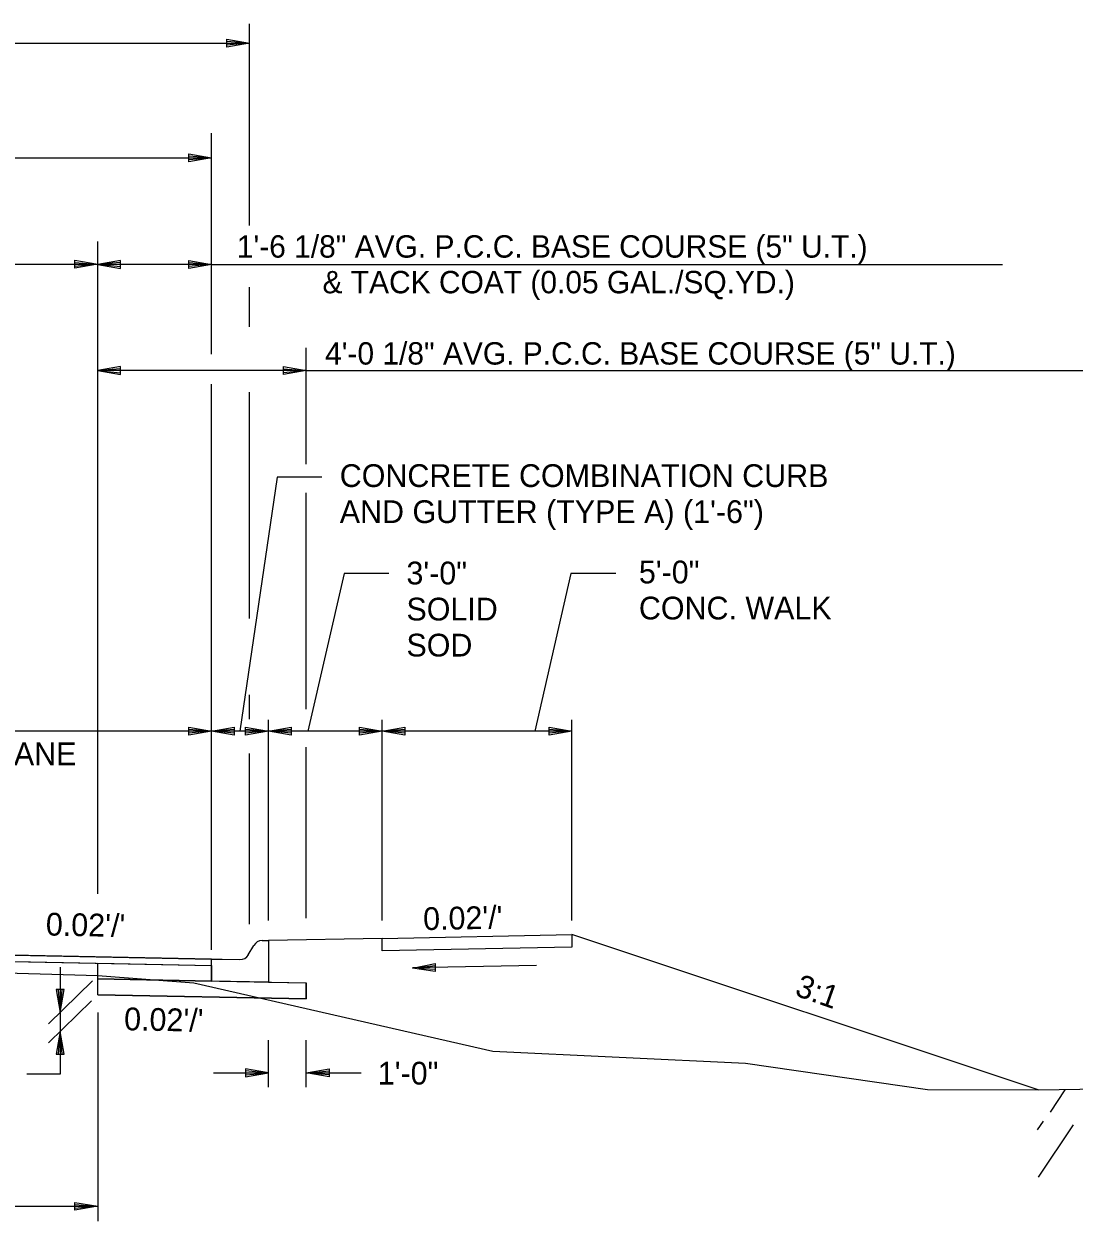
# Model space of a CAD drawing. Extents: x 1001270 to 1003428, y 1840152 to 1842912.
# Drawn here: x 1001348.15 to 1001375.83, y 1841972.67 to 1842004.22 of the extents above; entities that cross this region are included whole.
import ezdxf

# ---------------------------------------------------------------- set-up
doc = ezdxf.new("R2010")
doc.units = 0
for name, color, linetype in [('19', 7, 'Continuous'), ('20', 7, 'Continuous'), ('8', 7, 'Continuous')]:
    doc.layers.add(name, color=color, linetype=linetype)

# ---------------------------------------------------------------- blocks, each defined once
blk = doc.blocks.new('TM')
at = {"layer": '8'}
for p, q in [((-120.309, 21.181), (-119.787, -20.829)), ((0, 0), (-120.309, 21.181)), ((-31.382, 2.945), (-120.176, 10.512)), ((-119.787, -20.829), (0, 0)), ((-119.911, -10.826), (-31.307, -3.057))]:
    blk.add_line(p, q, dxfattribs=at)

msp = doc.modelspace()

# ---------------------------------------------------------------- linework, layer by layer
at = {"layer": '19'}
for p, q in [((1001354.093, 1841998.907), (1001354.093, 1842004.222)), ((1001353.493, 1842003.614), (1001353.493, 1842003.824)), ((1001353.493, 1842003.824), (1001354.093, 1842003.719)), ((1001353.493, 1842003.769), (1001353.933, 1842003.734)), ((1001316.093, 1842003.719), (1001354.093, 1842003.719)), ((1001354.093, 1842003.719), (1001353.493, 1842003.614)), ((1001353.933, 1842003.704), (1001353.493, 1842003.664)), ((1001353.092, 1841995.519), (1001353.092, 1842001.344)), ((1001317.092, 1842000.692), (1001353.092, 1842000.692)), ((1001352.493, 1842000.587), (1001352.493, 1842000.797)), ((1001352.493, 1842000.797), (1001353.093, 1842000.692)), ((1001352.493, 1842000.742), (1001352.933, 1842000.707)), ((1001353.093, 1842000.692), (1001352.493, 1842000.587)), ((1001352.933, 1842000.677), (1001352.493, 1842000.637)), ((1001350.092, 1841981.291), (1001350.092, 1841998.484)), ((1001320.092, 1841997.886), (1001350.092, 1841997.886)), ((1001349.492, 1841997.781), (1001349.492, 1841997.991)), ((1001349.492, 1841997.991), (1001350.092, 1841997.886)), ((1001349.492, 1841997.936), (1001349.932, 1841997.901)), ((1001350.092, 1841997.886), (1001349.492, 1841997.781)), ((1001349.932, 1841997.871), (1001349.492, 1841997.831)), ((1001350.692, 1841997.989), (1001350.092, 1841997.884)), ((1001353.092, 1841997.884), (1001350.092, 1841997.884)), ((1001350.092, 1841997.884), (1001350.692, 1841997.779)), ((1001350.692, 1841997.934), (1001350.252, 1841997.899)), ((1001350.252, 1841997.869), (1001350.692, 1841997.829)), ((1001350.692, 1841997.779), (1001350.692, 1841997.989)), ((1001352.492, 1841997.779), (1001352.492, 1841997.989)), ((1001352.492, 1841997.989), (1001353.092, 1841997.884)), ((1001352.492, 1841997.934), (1001352.932, 1841997.899)), ((1001353.092, 1841997.884), (1001352.492, 1841997.779)), ((1001352.932, 1841997.869), (1001352.492, 1841997.829)), ((1001353.092, 1841997.884), (1001373.944, 1841997.884)), ((1001354.092, 1841996.238), (1001354.092, 1841997.28)), ((1001355.592, 1841992.621), (1001355.592, 1841995.684)), ((1001350.692, 1841995.189), (1001350.092, 1841995.084)), ((1001355.592, 1841995.084), (1001350.092, 1841995.084)), ((1001350.092, 1841995.084), (1001350.692, 1841994.979)), ((1001350.692, 1841995.134), (1001350.252, 1841995.099)), ((1001350.252, 1841995.069), (1001350.692, 1841995.029)), ((1001350.692, 1841994.979), (1001350.692, 1841995.189)), ((1001354.992, 1841994.979), (1001354.992, 1841995.189)), ((1001354.992, 1841995.189), (1001355.592, 1841995.084)), ((1001354.992, 1841995.134), (1001355.432, 1841995.099)), ((1001355.592, 1841995.084), (1001354.992, 1841994.979)), ((1001355.432, 1841995.069), (1001354.992, 1841995.029)), ((1001355.592, 1841995.084), (1001376.275, 1841995.084)), ((1001353.092, 1841979.814), (1001353.092, 1841994.724)), ((1001354.092, 1841988.55), (1001354.092, 1841994.519)), ((1001354.823, 1841992.275), (1001353.835, 1841985.583)), ((1001356.002, 1841992.275), (1001354.823, 1841992.275)), ((1001355.592, 1841986.161), (1001355.592, 1841991.861)), ((1001356.587, 1841989.74), (1001355.63, 1841985.583)), ((1001357.766, 1841989.74), (1001356.587, 1841989.74)), ((1001362.569, 1841989.74), (1001361.613, 1841985.583)), ((1001363.748, 1841989.74), (1001362.569, 1841989.74)), ((1001354.092, 1841985.894), (1001354.092, 1841986.541)), ((1001353.092, 1841979.814), (1001353.092, 1841985.883)), ((1001354.592, 1841980.592), (1001354.592, 1841985.883)), ((1001357.592, 1841980.592), (1001357.592, 1841985.883)), ((1001362.592, 1841980.592), (1001362.592, 1841985.883)), ((1001353.092, 1841985.583), (1001341.092, 1841985.583)), ((1001352.492, 1841985.478), (1001352.492, 1841985.688)), ((1001352.492, 1841985.688), (1001353.092, 1841985.583)), ((1001352.492, 1841985.633), (1001352.932, 1841985.598)), ((1001353.092, 1841985.583), (1001352.492, 1841985.478)), ((1001352.932, 1841985.568), (1001352.492, 1841985.528)), ((1001353.092, 1841985.583), (1001353.692, 1841985.688)), ((1001362.592, 1841985.583), (1001353.092, 1841985.583)), ((1001353.692, 1841985.478), (1001353.092, 1841985.583)), ((1001353.252, 1841985.598), (1001353.692, 1841985.633)), ((1001353.692, 1841985.528), (1001353.252, 1841985.568)), ((1001353.692, 1841985.688), (1001353.692, 1841985.478)), ((1001353.992, 1841985.478), (1001353.992, 1841985.688)), ((1001353.992, 1841985.688), (1001354.592, 1841985.583)), ((1001353.992, 1841985.633), (1001354.432, 1841985.598)), ((1001354.592, 1841985.583), (1001353.992, 1841985.478)), ((1001354.432, 1841985.568), (1001353.992, 1841985.528)), ((1001354.592, 1841985.583), (1001355.192, 1841985.688)), ((1001355.192, 1841985.478), (1001354.592, 1841985.583)), ((1001354.752, 1841985.598), (1001355.192, 1841985.633)), ((1001355.192, 1841985.528), (1001354.752, 1841985.568)), ((1001355.192, 1841985.688), (1001355.192, 1841985.478)), ((1001356.992, 1841985.478), (1001356.992, 1841985.688)), ((1001356.992, 1841985.688), (1001357.592, 1841985.583)), ((1001356.992, 1841985.633), (1001357.432, 1841985.598)), ((1001357.592, 1841985.583), (1001356.992, 1841985.478)), ((1001357.432, 1841985.568), (1001356.992, 1841985.528)), ((1001357.592, 1841985.583), (1001358.192, 1841985.688)), ((1001358.192, 1841985.478), (1001357.592, 1841985.583)), ((1001357.752, 1841985.598), (1001358.192, 1841985.633)), ((1001358.192, 1841985.528), (1001357.752, 1841985.568)), ((1001358.192, 1841985.688), (1001358.192, 1841985.478)), ((1001361.992, 1841985.478), (1001361.992, 1841985.688)), ((1001361.992, 1841985.688), (1001362.592, 1841985.583)), ((1001361.992, 1841985.633), (1001362.432, 1841985.598)), ((1001362.592, 1841985.583), (1001361.992, 1841985.478)), ((1001362.432, 1841985.568), (1001361.992, 1841985.528)), ((1001355.592, 1841980.647), (1001355.592, 1841985.157)), ((1001354.092, 1841980.489), (1001354.092, 1841984.987)), ((1001357.593, 1841980.119), (1001354.592, 1841980.059)), ((1001357.593, 1841980.119), (1001362.592, 1841980.219)), ((1001357.593, 1841979.786), (1001357.593, 1841980.119)), ((1001357.593, 1841980.119), (1001357.593, 1841980.119)), ((1001362.592, 1841980.219), (1001362.592, 1841979.886)), ((1001374.88, 1841976.122), (1001362.592, 1841980.219)), ((1001335.092, 1841979.934), (1001353.092, 1841979.574)), ((1001354.063, 1841979.683), (1001354.209, 1841979.934)), ((1001354.425, 1841980.059), (1001354.592, 1841980.059)), ((1001354.592, 1841980.059), (1001354.592, 1841979.725)), ((1001362.592, 1841979.886), (1001357.593, 1841979.786)), ((1001335.092, 1841979.767), (1001353.092, 1841979.407)), ((1001353.092, 1841979.574), (1001353.376, 1841979.568)), ((1001353.376, 1841979.568), (1001353.376, 1841979.568)), ((1001353.376, 1841979.568), (1001353.376, 1841979.568)), ((1001353.376, 1841979.568), (1001353.842, 1841979.559)), ((1001354.592, 1841979.725), (1001354.592, 1841979.544)), ((1001354.592, 1841979.544), (1001354.592, 1841978.964)), ((1001350.092, 1841978.634), (1001350.092, 1841979.467)), ((1001350.092, 1841979.467), (1001353.092, 1841979.407)), ((1001350.092, 1841979.05), (1001350.092, 1841979.467)), ((1001350.092, 1841979.467), (1001350.092, 1841979.467)), ((1001353.092, 1841979.407), (1001353.092, 1841978.99)), ((1001349.954, 1841979.002), (1001348.792, 1841977.864)), ((1001350.092, 1841979.05), (1001353.092, 1841978.99)), ((1001353.092, 1841978.99), (1001350.092, 1841979.05)), ((1001350.092, 1841979.05), (1001355.592, 1841978.943)), ((1001350.092, 1841978.634), (1001350.092, 1841979.05)), ((1001350.092, 1841979.05), (1001350.092, 1841979.05)), ((1001354.592, 1841978.964), (1001353.092, 1841978.993)), ((1001354.592, 1841978.964), (1001355.592, 1841978.943)), ((1001355.592, 1841978.524), (1001355.592, 1841978.943)), ((1001355.592, 1841978.943), (1001355.592, 1841978.524)), ((1001349.207, 1841978.767), (1001348.997, 1841978.767)), ((1001348.997, 1841978.767), (1001349.102, 1841978.167)), ((1001349.052, 1841978.767), (1001349.087, 1841978.327)), ((1001349.102, 1841978.167), (1001349.207, 1841978.767)), ((1001349.117, 1841978.327), (1001349.157, 1841978.767)), ((1001350.092, 1841978.634), (1001355.592, 1841978.524)), ((1001355.592, 1841978.524), (1001350.092, 1841978.634)), ((1001349.928, 1841978.473), (1001348.792, 1841977.361)), ((1001350.092, 1841978.167), (1001350.092, 1841972.667)), ((1001349.102, 1841977.664), (1001348.997, 1841977.064)), ((1001349.207, 1841977.064), (1001349.102, 1841977.664)), ((1001349.087, 1841977.504), (1001349.047, 1841977.064)), ((1001349.152, 1841977.064), (1001349.117, 1841977.504)), ((1001354.592, 1841976.194), (1001354.592, 1841977.432)), ((1001355.592, 1841976.194), (1001355.592, 1841977.432)), ((1001348.997, 1841977.064), (1001349.207, 1841977.064)), ((1001353.992, 1841976.678), (1001353.992, 1841976.468)), ((1001354.592, 1841976.572), (1001353.992, 1841976.678)), ((1001353.992, 1841976.678), (1001353.992, 1841976.468)), ((1001354.592, 1841976.572), (1001353.992, 1841976.678)), ((1001355.592, 1841976.572), (1001356.192, 1841976.678)), ((1001355.592, 1841976.572), (1001356.192, 1841976.678)), ((1001356.192, 1841976.678), (1001356.192, 1841976.468)), ((1001356.192, 1841976.678), (1001356.192, 1841976.468)), ((1001349.102, 1841976.536), (1001348.227, 1841976.536)), ((1001353.143, 1841976.572), (1001354.592, 1841976.572)), ((1001353.143, 1841976.572), (1001354.592, 1841976.572)), ((1001354.432, 1841976.587), (1001353.992, 1841976.623)), ((1001354.432, 1841976.587), (1001353.992, 1841976.623)), ((1001353.992, 1841976.468), (1001354.592, 1841976.572)), ((1001353.992, 1841976.468), (1001354.592, 1841976.572)), ((1001353.992, 1841976.518), (1001354.432, 1841976.557)), ((1001353.992, 1841976.518), (1001354.432, 1841976.557)), ((1001356.192, 1841976.468), (1001355.592, 1841976.572)), ((1001355.592, 1841976.572), (1001357.041, 1841976.572)), ((1001356.192, 1841976.468), (1001355.592, 1841976.572)), ((1001355.592, 1841976.572), (1001357.041, 1841976.572)), ((1001355.752, 1841976.587), (1001356.192, 1841976.623)), ((1001355.752, 1841976.587), (1001356.192, 1841976.623)), ((1001356.192, 1841976.518), (1001355.752, 1841976.557)), ((1001356.192, 1841976.518), (1001355.752, 1841976.557)), ((1001374.88, 1841976.122), (1001387.086, 1841976.326)), ((1001375.207, 1841975.539), (1001375.599, 1841976.122)), ((1001374.867, 1841975.072), (1001375.021, 1841975.297)), ((1001374.89, 1841973.823), (1001375.816, 1841975.205)), ((1001349.492, 1841972.95), (1001349.492, 1841973.16)), ((1001349.492, 1841973.16), (1001350.092, 1841973.055)), ((1001320.092, 1841973.055), (1001350.092, 1841973.055)), ((1001349.492, 1841973.105), (1001349.932, 1841973.07)), ((1001350.092, 1841973.055), (1001349.492, 1841972.95)), ((1001349.932, 1841973.04), (1001349.492, 1841973))]:
    msp.add_line(p, q, dxfattribs=at)
for points in [[(1001292.953, 1841985.11), (1001296.602, 1841984.886), (1001300.785, 1841984.235), (1001304.507, 1841983.003), (1001306.659, 1841982.399), (1001318.238, 1841979.073), (1001320.092, 1841979.095), (1001335.185, 1841979.572), (1001350.092, 1841979.136), (1001352.626, 1841978.949), (1001360.512, 1841977.149), (1001367.17, 1841976.831), (1001371.963, 1841976.134), (1001374.88, 1841976.122)], [(1001353.092, 1841978.993), (1001353.092, 1841979.157), (1001353.092, 1841979.407), (1001353.092, 1841979.574)], [(1001349.102, 1841979.361), (1001349.102, 1841976.536)]]:
    msp.add_lwpolyline(points, dxfattribs=at)
msp.add_lwpolyline([(1001335.092, 1841979.934), (1001317.092, 1841979.574), (1001317.092, 1841979.407), (1001335.092, 1841979.767), (1001353.092, 1841979.407), (1001353.092, 1841979.574)], close=True, dxfattribs=at)
for centre, start, end in [((1001354.425, 1841979.809), 90, 149.8381), ((1001353.847, 1841979.809), 268.8542, 329.8365)]:
    msp.add_arc(centre, 0.25, start, end, dxfattribs=at)
at = {"layer": '20'}
msp.add_line((1001361.66, 1841979.404), (1001358.39, 1841979.339), dxfattribs=at)

# ---------------------------------------------------------------- block references
at = {"layer": '19', "xscale": 0.0050063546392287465, "yscale": -0.0050063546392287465, "rotation": -178.8781640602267}
msp.add_blockref('TM', (1001358.39, 1841979.336), dxfattribs=at)

# ---------------------------------------------------------------- texts
at = {"layer": '19'}
for s, height, p in [('1\'-6 1/8" AVG. P.C.C. BASE COURSE (5" U.T.)', 0.59001, (1001353.761, 1841998.062)), ('& TACK COAT (0.05 GAL./SQ.YD.)', 0.59001, (1001356.019, 1841997.122)), ('4\'-0 1/8" AVG. P.C.C. BASE COURSE (5" U.T.)', 0.59001, (1001356.087, 1841995.243)), ('CONCRETE COMBINATION CURB', 0.6, (1001356.473, 1841992.016)), ('AND GUTTER (TYPE A) (1\'-6")', 0.6, (1001356.473, 1841991.066)), ('3\'-0"', 0.6, (1001358.231, 1841989.448)), ('5\'-0"', 0.6, (1001364.359, 1841989.475)), ('SOLID ', 0.6, (1001358.231, 1841988.498)), ('CONC. WALK', 0.6, (1001364.359, 1841988.525)), ('SOD', 0.6, (1001358.231, 1841987.548)), ('TRAVEL LANE', 0.6, (1001344.092, 1841984.683))]:
    msp.add_text(s, height=height, dxfattribs=at).set_placement(p)
for s, rotation, p in [("0.02'/'", 358.8542, (1001348.721, 1841980.195)), ("0.02'/'", 1.1419, (1001358.677, 1841980.335)), ('3:1', 340.4943, (1001368.443, 1841978.622)), ("0.02'/'", 358.8542, (1001350.784, 1841977.698)), ('1\'-0"', 360, (1001357.476, 1841976.265))]:
    msp.add_text(s, height=0.6, rotation=rotation, dxfattribs=at).set_placement(p)

doc.saveas('drawing.dxf')
